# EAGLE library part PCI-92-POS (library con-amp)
PCI-SLOT 92 Dual Position 0.05 Series Standard Edge Source: http://catalog.tycoelectronics.com .. ENG_CD_145165_G.pdf
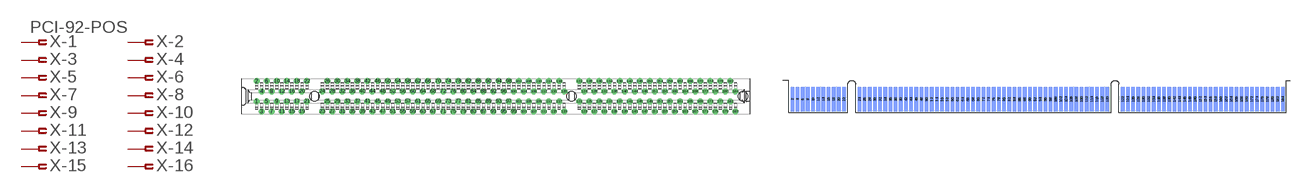
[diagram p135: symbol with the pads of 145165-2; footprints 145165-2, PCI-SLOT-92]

Designator prefix X; gates -1=PIN-FV -2=PIN-F -3=PIN-F -4=PIN-F -5=PIN-F -6=PIN-F -7=PIN-F -8=PIN-F -9=PIN-F -10=PIN-F -11=PIN-F -12=PIN-F -13=PIN-F -14=PIN-F -15=PIN-F -16=PIN-F -17=PIN-F -18=PIN-F -19=PIN-F -20=PIN-F -21=PIN-F -22=PIN-F -23=PIN-F -24=PIN-F -25=PIN-F -26=PIN-F -27=PIN-F -28=PIN-F -29=PIN-F -30=PIN-F -31=PIN-F -32=PIN-F -33=PIN-F -34=PIN-F -35=PIN-F -36=PIN-F -37=PIN-F -38=PIN-F -39=PIN-F -40=PIN-F -41=PIN-F -42=PIN-F -43=PIN-F -44=PIN-F -45=PIN-F -46=PIN-F -47=PIN-F -48=PIN-F -49=PIN-F -50=PIN-F -51=PIN-F -52=PIN-F -53=PIN-F -54=PIN-F -55=PIN-F -56=PIN-F -57=PIN-F -58=PIN-F -59=PIN-F -60=PIN-F -61=PIN-F -62=PIN-F -63=PIN-F -64=PIN-F -65=PIN-F -66=PIN-F -67=PIN-F -68=PIN-F -69=PIN-F -70=PIN-F -71=PIN-F -72=PIN-F -73=PIN-F -74=PIN-F -75=PIN-F -76=PIN-F -77=PIN-F -78=PIN-F -79=PIN-F -80=PIN-F -81=PIN-F -82=PIN-F -83=PIN-F -84=PIN-F -85=PIN-F -86=PIN-F -87=PIN-F -88=PIN-F -89=PIN-F -90=PIN-F -91=PIN-F -92=PIN-F -93=PIN-F -94=PIN-F -95=PIN-F -96=PIN-F -97=PIN-F -98=PIN-F -99=PIN-F -100=PIN-F -101=PIN-F -102=PIN-F -103=PIN-F -104=PIN-F -105=PIN-F -106=PIN-F -107=PIN-F -108=PIN-F -109=PIN-F -110=PIN-F -111=PIN-F -112=PIN-F -113=PIN-F -114=PIN-F -115=PIN-F -116=PIN-F -117=PIN-F -118=PIN-F -119=PIN-F -120=PIN-F -121=PIN-F -122=PIN-F -123=PIN-F -124=PIN-F -125=PIN-F -126=PIN-F -127=PIN-F -128=PIN-F -129=PIN-F -130=PIN-F -131=PIN-F -132=PIN-F -133=PIN-F -134=PIN-F -135=PIN-F -136=PIN-F -137=PIN-F -138=PIN-F -139=PIN-F -140=PIN-F -141=PIN-F -142=PIN-F -143=PIN-F -144=PIN-F -145=PIN-F -146=PIN-F -147=PIN-F -148=PIN-F -149=PIN-F -150=PIN-F -151=PIN-F -152=PIN-F -153=PIN-F -154=PIN-F -155=PIN-F -156=PIN-F -157=PIN-F -158=PIN-F -159=PIN-F -160=PIN-F -161=PIN-F -162=PIN-F -163=PIN-F -164=PIN-F -165=PIN-F -166=PIN-F -167=PIN-F -168=PIN-F -169=PIN-F -170=PIN-F -171=PIN-F -172=PIN-F -173=PIN-F -174=PIN-F -175=PIN-F -176=PIN-F -177=PIN-F -178=PIN-F -179=PIN-F -180=PIN-F -181=PIN-F -182=PIN-F -183=PIN-F -184=PIN-F

## PCI-92-POS-145165 (MPN: 145165-2; OC_FARNELL: unknown; OC_NEWARK: 17R3223)  [145165-2]
1  -1:1  pas
2  -2:1  pas
3  -3:1  pas
4  -4:1  pas
5  -5:1  pas
6  -6:1  pas
7  -7:1  pas
8  -8:1  pas
9  -9:1  pas
10  -10:1  pas
11  -11:1  pas
12  -12:1  pas
13  -13:1  pas
14  -14:1  pas
15  -15:1  pas
16  -16:1  pas
17  -17:1  pas
18  -18:1  pas
19  -19:1  pas
20  -20:1  pas
21  -21:1  pas
22  -22:1  pas
23  -23:1  pas
24  -24:1  pas
25  -25:1  pas
26  -26:1  pas
27  -27:1  pas
28  -28:1  pas
29  -29:1  pas
30  -30:1  pas
31  -31:1  pas
32  -32:1  pas
33  -33:1  pas
34  -34:1  pas
35  -35:1  pas
36  -36:1  pas
37  -37:1  pas
38  -38:1  pas
39  -39:1  pas
40  -40:1  pas
41  -41:1  pas
42  -42:1  pas
43  -43:1  pas
44  -44:1  pas
45  -45:1  pas
46  -46:1  pas
47  -47:1  pas
48  -48:1  pas
49  -49:1  pas
50  -50:1  pas
51  -51:1  pas
52  -52:1  pas
53  -53:1  pas
54  -54:1  pas
55  -55:1  pas
56  -56:1  pas
57  -57:1  pas
58  -58:1  pas
59  -59:1  pas
60  -60:1  pas
61  -61:1  pas
62  -62:1  pas
63  -63:1  pas
64  -64:1  pas
65  -65:1  pas
66  -66:1  pas
67  -67:1  pas
68  -68:1  pas
69  -69:1  pas
70  -70:1  pas
71  -71:1  pas
72  -72:1  pas
73  -73:1  pas
74  -74:1  pas
75  -75:1  pas
76  -76:1  pas
77  -77:1  pas
78  -78:1  pas
79  -79:1  pas
80  -80:1  pas
81  -81:1  pas
82  -82:1  pas
83  -83:1  pas
84  -84:1  pas
85  -85:1  pas
86  -86:1  pas
87  -87:1  pas
88  -88:1  pas
89  -89:1  pas
90  -90:1  pas
91  -91:1  pas
92  -92:1  pas
93  -93:1  pas
94  -94:1  pas
95  -95:1  pas
96  -96:1  pas
97  -97:1  pas
98  -98:1  pas
99  -99:1  pas
100  -100:1  pas
101  -101:1  pas
102  -102:1  pas
103  -103:1  pas
104  -104:1  pas
105  -105:1  pas
106  -106:1  pas
107  -107:1  pas
108  -108:1  pas
109  -109:1  pas
110  -110:1  pas
111  -111:1  pas
112  -112:1  pas
113  -113:1  pas
114  -114:1  pas
115  -115:1  pas
116  -116:1  pas
117  -117:1  pas
118  -118:1  pas
119  -119:1  pas
120  -120:1  pas
121  -121:1  pas
122  -122:1  pas
123  -123:1  pas
124  -124:1  pas
125  -125:1  pas
126  -126:1  pas
127  -127:1  pas
128  -128:1  pas
129  -129:1  pas
130  -130:1  pas
131  -131:1  pas
132  -132:1  pas
133  -133:1  pas
134  -134:1  pas
135  -135:1  pas
136  -136:1  pas
137  -137:1  pas
138  -138:1  pas
139  -139:1  pas
140  -140:1  pas
141  -141:1  pas
142  -142:1  pas
143  -143:1  pas
144  -144:1  pas
145  -145:1  pas
146  -146:1  pas
147  -147:1  pas
148  -148:1  pas
149  -149:1  pas
150  -150:1  pas
151  -151:1  pas
152  -152:1  pas
153  -153:1  pas
154  -154:1  pas
155  -155:1  pas
156  -156:1  pas
157  -157:1  pas
158  -158:1  pas
159  -159:1  pas
160  -160:1  pas
161  -161:1  pas
162  -162:1  pas
163  -163:1  pas
164  -164:1  pas
165  -165:1  pas
166  -166:1  pas
167  -167:1  pas
168  -168:1  pas
169  -169:1  pas
170  -170:1  pas
171  -171:1  pas
172  -172:1  pas
173  -173:1  pas
174  -174:1  pas
175  -175:1  pas
176  -176:1  pas
177  -177:1  pas
178  -178:1  pas
179  -179:1  pas
180  -180:1  pas
181  -181:1  pas
182  -182:1  pas
183  -183:1  pas
184  -184:1  pas

## PCI-92-POS-SLOT (OC_FARNELL: unknown; OC_NEWARK: unknown)  [PCI-SLOT-92]
Pads as for 145165-2

## Footprint 145165-2 (pad centres in mm)
PCI Connector 92 Dual Pos. Standard Edge .050 Series PCI Source: http://catalog.tycoelectronics.com .. END_CD_145165_G.pdf
drill 1 pad 1.2 round: 1 0,-1.27; 2 0,3.81; 3 1.27,-3.81; 4 1.27,1.27; 5 2.54,-1.27; 6 2.54,3.81; 7 3.81,-3.81; 8 3.81,1.27; 9 5.08,-1.27; 10 5.08,3.81; 11 6.35,-3.81; 12 6.35,1.27; 13 7.62,-1.27; 14 7.62,3.81; 15 8.89,-3.81; 16 8.89,1.27; 17 10.16,-1.27; 18 10.16,3.81; 19 11.43,-3.81; 20 11.43,1.27; 21 12.7,-1.27; 22 12.7,3.81; 23 16.51,-3.81; 24 16.51,1.27; 25 17.78,-1.27; 26 17.78,3.81; 27 19.05,-3.81; 28 19.05,1.27; 29 20.32,-1.27; 30 20.32,3.81; 31 21.59,-3.81; 32 21.59,1.27; 33 22.86,-1.27; 34 22.86,3.81; 35 24.13,-3.81; 36 24.13,1.27; 37 25.4,-1.27; 38 25.4,3.81; 39 26.67,-3.81; 40 26.67,1.27; 41 27.94,-1.27; 42 27.94,3.81; 43 29.21,-3.81; 44 29.21,1.27; 45 30.48,-1.27; 46 30.48,3.81; 47 31.75,-3.81; 48 31.75,1.27; 49 33.02,-1.27; 50 33.02,3.81; 51 34.29,-3.81; 52 34.29,1.27; 53 35.56,-1.27; 54 35.56,3.81; 55 36.83,-3.81; 56 36.83,1.27; 57 38.1,-1.27; 58 38.1,3.81; 59 39.37,-3.81; 60 39.37,1.27; 61 40.64,-1.27; 62 40.64,3.81; 63 41.91,-3.81; 64 41.91,1.27; 65 43.18,-1.27; 66 43.18,3.81; 67 44.45,-3.81; 68 44.45,1.27; 69 45.72,-1.27; 70 45.72,3.81; 71 46.99,-3.81; 72 46.99,1.27; 73 48.26,-1.27; 74 48.26,3.81; 75 49.53,-3.81; 76 49.53,1.27; 77 50.8,-1.27; 78 50.8,3.81; 79 52.07,-3.81; 80 52.07,1.27; 81 53.34,-1.27; 82 53.34,3.81; 83 54.61,-3.81; 84 54.61,1.27; 85 55.88,-1.27; 86 55.88,3.81; 87 57.15,-3.81; 88 57.15,1.27; 89 58.42,-1.27; 90 58.42,3.81; 91 59.69,-3.81; 92 59.69,1.27; 93 60.96,-1.27; 94 60.96,3.81; 95 62.23,-3.81; 96 62.23,1.27; 97 63.5,-1.27; 98 63.5,3.81; 99 64.77,-3.81; 100 64.77,1.27; 101 66.04,-1.27; 102 66.04,3.81; 103 67.31,-3.81; 104 67.31,1.27; 105 68.58,-1.27; 106 68.58,3.81; 107 69.85,-3.81; 108 69.85,1.27; 109 71.12,-1.27; 110 71.12,3.81; 111 72.39,-3.81; 112 72.39,1.27; 113 73.66,-1.27; 114 73.66,3.81; 115 74.93,-3.81; 116 74.93,1.27; 117 76.2,-1.27; 118 76.2,3.81; 119 77.47,-3.81; 120 77.47,1.27; 121 81.28,-1.27; 122 81.28,3.81; 123 82.55,-3.81; 124 82.55,1.27; 125 83.82,-1.27; 126 83.82,3.81; 127 85.09,-3.81; 128 85.09,1.27; 129 86.36,-1.27; 130 86.36,3.81; 131 87.63,-3.81; 132 87.63,1.27; 133 88.9,-1.27; 134 88.9,3.81; 135 90.17,-3.81; 136 90.17,1.27; 137 91.44,-1.27; 138 91.44,3.81; 139 92.71,-3.81; 140 92.71,1.27; 141 93.98,-1.27; 142 93.98,3.81; 143 95.25,-3.81; 144 95.25,1.27; 145 96.52,-1.27; 146 96.52,3.81; 147 97.79,-3.81; 148 97.79,1.27; 149 99.06,-1.27; 150 99.06,3.81; 151 100.33,-3.81; 152 100.33,1.27; 153 101.6,-1.27; 154 101.6,3.81; 155 102.87,-3.81; 156 102.87,1.27; 157 104.14,-1.27; 158 104.14,3.81; 159 105.41,-3.81; 160 105.41,1.27; 161 106.68,-1.27; 162 106.68,3.81; 163 107.95,-3.81; 164 107.95,1.27; 165 109.22,-1.27; 166 109.22,3.81; 167 110.49,-3.81; 168 110.49,1.27; 169 111.76,-1.27; 170 111.76,3.81; 171 113.03,-3.81; 172 113.03,1.27; 173 114.3,-1.27; 174 114.3,3.81; 175 115.57,-3.81; 176 115.57,1.27; 177 116.84,-1.27; 178 116.84,3.81; 179 118.11,-3.81; 180 118.11,1.27; 181 119.38,-1.27; 182 119.38,3.81; 183 120.65,-3.81; 184 120.65,1.27
hole 2.44 at 14.6,0
hole 2.44 at 79.37,0
hole 2.44 at 122.55,0

## Footprint PCI-SLOT-92 (pad centres in mm)
PCI Connector 92 Dual Position 0.05 Series Standard Edge Source: http://catalog.tycoelectronics.com .. ENG_CD_145165_G.pdf
smd 0.91 x 6: 1 0,3.22; 3 1.27,3.22; 5 2.54,3.22; 7 3.81,3.22; 9 5.08,3.22; 11 6.35,3.22; 13 7.62,3.22; 15 8.89,3.22; 17 10.16,3.22; 19 11.43,3.22; 21 12.7,3.22; 23 16.51,3.22; 25 17.78,3.22; 27 19.05,3.22; 29 20.32,3.22; 31 21.59,3.22; 33 22.86,3.22; 35 24.13,3.22; 37 25.4,3.22; 39 26.67,3.22; 41 27.94,3.22; 43 29.21,3.22; 45 30.48,3.22; 47 31.75,3.22; 49 33.02,3.22; 51 34.29,3.22; 53 35.56,3.22; 55 36.83,3.22; 57 38.1,3.22; 59 39.37,3.22; 61 40.64,3.22; 63 41.91,3.22; 65 43.18,3.22; 67 44.45,3.22; 69 45.72,3.22; 71 46.99,3.22; 73 48.26,3.22; 75 49.53,3.22; 77 50.8,3.22; 79 52.07,3.22; 81 53.34,3.22; 83 54.61,3.22; 85 55.88,3.22; 87 57.15,3.22; 89 58.42,3.22; 91 59.69,3.22; 93 60.96,3.22; 95 62.23,3.22; 97 63.5,3.22; 99 64.77,3.22; 101 66.04,3.22; 103 67.31,3.22; 105 68.58,3.22; 107 69.85,3.22; 109 71.12,3.22; 111 72.39,3.22; 113 73.66,3.22; 115 74.93,3.22; 117 76.2,3.22; 119 77.47,3.22; 121 81.28,3.22; 123 82.55,3.22; 125 83.82,3.22; 127 85.09,3.22; 129 86.36,3.22; 131 87.63,3.22; 133 88.9,3.22; 135 90.17,3.22; 137 91.44,3.22; 139 92.71,3.22; 141 93.98,3.22; 143 95.25,3.22; 145 96.52,3.22; 147 97.79,3.22; 149 99.06,3.22; 151 100.33,3.22; 153 101.6,3.22; 155 102.87,3.22; 157 104.14,3.22; 159 105.41,3.22; 161 106.68,3.22; 163 107.95,3.22; 165 109.22,3.22; 167 110.49,3.22; 169 111.76,3.22; 171 113.03,3.22; 173 114.3,3.22; 175 115.57,3.22; 177 116.84,3.22; 179 118.11,3.22; 181 119.38,3.22; 183 120.65,3.22
smd 0.91 x 6 bottom: 2 0,3.22; 4 1.27,3.22; 6 2.54,3.22; 8 3.81,3.22; 10 5.08,3.22; 12 6.35,3.22; 14 7.62,3.22; 16 8.89,3.22; 18 10.16,3.22; 20 11.43,3.22; 22 12.7,3.22; 24 16.51,3.22; 26 17.78,3.22; 28 19.05,3.22; 30 20.32,3.22; 32 21.59,3.22; 34 22.86,3.22; 36 24.13,3.22; 38 25.4,3.22; 40 26.67,3.22; 42 27.94,3.22; 44 29.21,3.22; 46 30.48,3.22; 48 31.75,3.22; 50 33.02,3.22; 52 34.29,3.22; 54 35.56,3.22; 56 36.83,3.22; 58 38.1,3.22; 60 39.37,3.22; 62 40.64,3.22; 64 41.91,3.22; 66 43.18,3.22; 68 44.45,3.22; 70 45.72,3.22; 72 46.99,3.22; 74 48.26,3.22; 76 49.53,3.22; 78 50.8,3.22; 80 52.07,3.22; 82 53.34,3.22; 84 54.61,3.22; 86 55.88,3.22; 88 57.15,3.22; 90 58.42,3.22; 92 59.69,3.22; 94 60.96,3.22; 96 62.23,3.22; 98 63.5,3.22; 100 64.77,3.22; 102 66.04,3.22; 104 67.31,3.22; 106 68.58,3.22; 108 69.85,3.22; 110 71.12,3.22; 112 72.39,3.22; 114 73.66,3.22; 116 74.93,3.22; 118 76.2,3.22; 120 77.47,3.22; 122 81.28,3.22; 124 82.55,3.22; 126 83.82,3.22; 128 85.09,3.22; 130 86.36,3.22; 132 87.63,3.22; 134 88.9,3.22; 136 90.17,3.22; 138 91.44,3.22; 140 92.71,3.22; 142 93.98,3.22; 144 95.25,3.22; 146 96.52,3.22; 148 97.79,3.22; 150 99.06,3.22; 152 100.33,3.22; 154 101.6,3.22; 156 102.87,3.22; 158 104.14,3.22; 160 105.41,3.22; 162 106.68,3.22; 164 107.95,3.22; 166 109.22,3.22; 168 110.49,3.22; 170 111.76,3.22; 172 113.03,3.22; 174 114.3,3.22; 176 115.57,3.22; 178 116.84,3.22; 180 118.11,3.22; 182 119.38,3.22; 184 120.65,3.22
